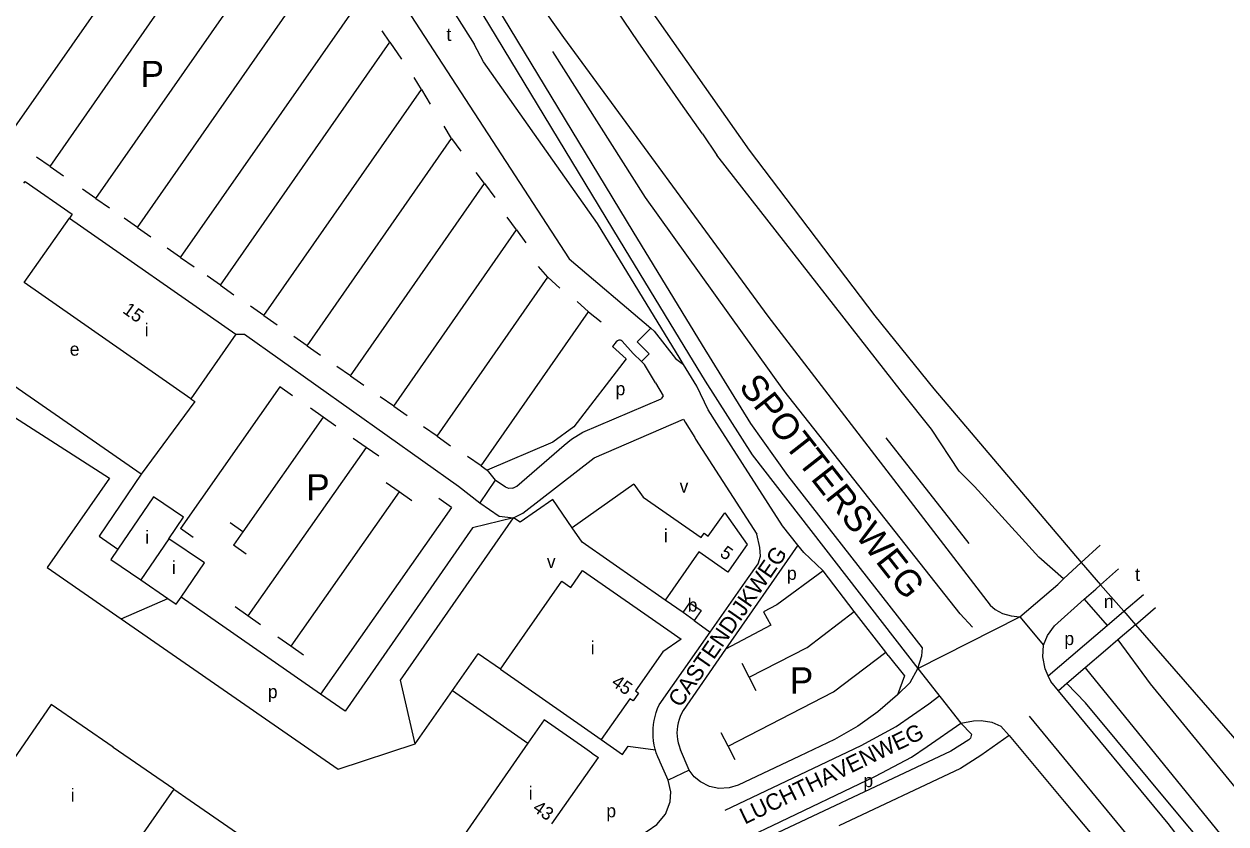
# Model space of a CAD drawing. Extents: x 154765 to 156627, y 383996 to 386132.
# Drawn here: x 155399 to 155766.1, y 385647.4 to 385891.7 of the extents above; entities that cross this region are included whole.
import ezdxf

# ---------------------------------------------------------------- set-up
doc = ezdxf.new("R2010")
doc.units = 0
for name, color, linetype in [('BLT_Basislijn', 7, 'Continuous'), ('BLT_Bebouwing', 7, 'Continuous'), ('BLT_Centroide', 7, 'Continuous'), ('BLT_Huisnummer', 7, 'Continuous'), ('BLT_Onderverdeling_panden', 7, 'Continuous'), ('BLT_Straatnaam', 7, 'Continuous'), ('BLT_Straatnaam_hoofdweg', 7, 'Continuous'), ('BLT_Tekst_parkeren', 7, 'Continuous'), ('BLT_Vlakafsluiter', 7, 'Continuous')]:
    doc.layers.add(name, color=color, linetype=linetype)

msp = doc.modelspace()

# ---------------------------------------------------------------- linework, layer by layer
at = {"layer": 'BLT_Basislijn'}
for p, q in [((155394.1, 385857.19), (155450.89, 385938.64)), ((155406.96, 385848.23), (155465.48, 385932.15)), ((155420.99, 385838.44), (155481.86, 385925.73)), ((155433.65, 385829.61), (155493.15, 385914.93)), ((155446.85, 385820.41), (155502.11, 385899.66)), ((155510.78, 385886.14), (155508.35, 385889.64)), ((155459.02, 385811.92), (155510.78, 385886.14)), ((155510.78, 385886.14), (155514.33, 385881.01)), ((155520.4, 385871.75), (155518.22, 385875.37)), ((155472.25, 385802.7), (155520.4, 385871.75)), ((155520.4, 385871.75), (155523.08, 385867.28)), ((155529.61, 385856.77), (155527.33, 385860.57)), ((155485.48, 385793.47), (155529.61, 385856.77)), ((155529.61, 385856.77), (155532.43, 385852.94)), ((155606.25, 385858.21), (155610.61, 385851.64)), ((155406.96, 385848.23), (155402.86, 385851.09)), ((155406.96, 385848.23), (155411.06, 385845.37)), ((155539.65, 385842.97), (155537.16, 385846.37)), ((155420.99, 385838.44), (155416.89, 385841.3)), ((155498.7, 385784.25), (155539.65, 385842.97)), ((155539.65, 385842.97), (155542.79, 385838.71)), ((155420.99, 385838.44), (155425.09, 385835.58)), ((155433.65, 385829.61), (155429.55, 385832.47)), ((155549.44, 385828.82), (155546.59, 385832.69)), ((155433.65, 385829.61), (155437.76, 385826.75)), ((155511.93, 385775.03), (155549.44, 385828.82)), ((155549.44, 385828.82), (155552.29, 385824.94)), ((155446.85, 385820.41), (155442.75, 385823.27)), ((155446.85, 385820.41), (155450.95, 385817.55)), ((155559.02, 385814.36), (155556.17, 385817.7)), ((155459.02, 385811.92), (155454.92, 385814.78)), ((155459.02, 385811.92), (155463.12, 385809.06)), ((155525.16, 385765.8), (155559.02, 385814.36)), ((155559.02, 385814.36), (155562.7, 385811.01)), ((155472.25, 385802.7), (155468.15, 385805.56)), ((155571.4, 385803.84), (155567.96, 385806.95)), ((155472.25, 385802.7), (155476.35, 385799.84)), ((155538.61, 385756.82), (155571.4, 385803.84)), ((155571.4, 385803.84), (155575.29, 385800.74)), ((155485.48, 385793.47), (155481.37, 385796.33)), ((155485.48, 385793.47), (155489.58, 385790.61)), ((155434.78, 385754.2), (155382.19, 385790.75)), ((155498.7, 385784.25), (155494.6, 385787.11)), ((155498.7, 385784.25), (155502.8, 385781.39)), ((155477.16, 385780.9), (155446.77, 385737.61)), ((155481.05, 385778.17), (155477.16, 385780.9)), ((155511.93, 385775.03), (155507.83, 385777.89)), ((155511.93, 385775.03), (155516.03, 385772.17)), ((155569.74, 385767.03), (155593.64, 385777.23)), ((155490.39, 385771.61), (155465.85, 385736.64)), ((155490.39, 385771.61), (155486.5, 385774.35)), ((155494.29, 385768.88), (155490.39, 385771.61)), ((155525.16, 385765.8), (155521.05, 385768.66)), ((155573.12, 385759.18), (155600.45, 385771.08)), ((155503.49, 385762.43), (155499.59, 385765.16)), ((155525.16, 385765.8), (155529.26, 385762.94)), ((155604.14, 385764.98), (155622.8, 385735.87)), ((155662.28, 385765.31), (155687.56, 385733.1)), ((155503.49, 385762.43), (155467.39, 385711)), ((155507.38, 385759.69), (155503.49, 385762.43)), ((155538.61, 385756.82), (155534.51, 385759.68)), ((155538.61, 385756.82), (155540.51, 385755.49)), ((155551.38, 385742.32), (155573.12, 385759.18)), ((155540.51, 385755.49), (155542.88, 385752.4)), ((155513.56, 385748.85), (155509.67, 385751.58)), ((155542.88, 385752.4), (155538.18, 385745.45)), ((155548.36, 385749.94), (155549.58, 385750.61)), ((155513.56, 385748.85), (155480.48, 385701.71)), ((155517.46, 385746.12), (155513.56, 385748.85)), ((155529.6, 385744.09), (155525.71, 385746.83)), ((155529.6, 385744.09), (155489.56, 385687.04)), ((155548.47, 385740.88), (155551.38, 385742.32)), ((155465.85, 385736.64), (155461.95, 385739.38)), ((155450.67, 385734.88), (155446.77, 385737.61)), ((155465.85, 385736.64), (155462.95, 385732.52)), ((155466.85, 385729.79), (155462.95, 385732.52)), ((155635.4, 385732.55), (155613.31, 385700.75)), ((155721.95, 385727.25), (155727.72, 385732.59)), ((155716.54, 385722.25), (155721.95, 385727.25)), ((155406.09, 385725.78), (155428.73, 385710.08)), ((155652.6, 385712.32), (155643.08, 385724.72)), ((155727.84, 385720.48), (155733.32, 385725.31)), ((155608.62, 385706.02), (155620, 385722.24)), ((155703.21, 385710.66), (155714.74, 385720.58)), ((155714.74, 385720.58), (155716.54, 385722.25)), ((155726.35, 385719.17), (155727.84, 385720.48)), ((155727.84, 385720.48), (155734.89, 385712.38)), ((155428.73, 385710.08), (155442.95, 385716.28)), ((155489.56, 385687.04), (155446.96, 385716.65)), ((155722.81, 385716.02), (155726.35, 385719.17)), ((155734.89, 385712.38), (155740.98, 385717.5)), ((155467.39, 385711), (155463.5, 385713.73)), ((155600.3, 385711.96), (155594.87, 385715.74)), ((155722.81, 385716.02), (155729.8, 385708.02)), ((155738.49, 385708.23), (155744.6, 385713.56)), ((155471.28, 385708.27), (155467.39, 385711)), ((155603.7, 385709.59), (155608.62, 385706.02)), ((155638.17, 385701.31), (155652.6, 385712.32)), ((155662.19, 385699.84), (155652.6, 385712.32)), ((155729.8, 385708.02), (155734.89, 385712.38)), ((155711.87, 385692.63), (155729.8, 385708.02)), ((155738.49, 385708.23), (155733.11, 385703.62)), ((155738.49, 385708.23), (155841.63, 385589.61)), ((155480.48, 385701.71), (155476.58, 385704.44)), ((155484.37, 385698.98), (155480.48, 385701.71)), ((155733.11, 385703.62), (155729.31, 385700.36)), ((155529.88, 385688.16), (155537.72, 385699.39)), ((155544.51, 385694.65), (155537.72, 385699.39)), ((155613.31, 385700.75), (155600.34, 385682.06)), ((155646.3, 385687.72), (155662.19, 385699.84)), ((155662.91, 385698.9), (155662.19, 385699.84)), ((155729.31, 385700.36), (155723.16, 385695.09)), ((155620.54, 385692.23), (155618.4, 385696.38)), ((155723.16, 385695.09), (155717.53, 385690.26)), ((155723.16, 385695.09), (155782.92, 385621.52)), ((155622.68, 385688.08), (155620.54, 385692.23)), ((155518.47, 385671.84), (155529.88, 385688.16)), ((155529.88, 385688.16), (155552.89, 385672.11)), ((155717.53, 385690.26), (155714.99, 385688.08)), ((155723.18, 385684.36), (155717.53, 385690.26)), ((155751.97, 385649.86), (155723.18, 385684.36)), ((155614.08, 385671.13), (155611.94, 385675.28)), ((155602.17, 385663.86), (155599.53, 385670.08)), ((155616.22, 385666.98), (155614.08, 385671.13)), ((155777.49, 385619.55), (155751.97, 385649.86))]:
    msp.add_line(p, q, dxfattribs=at)
for points in [[(155436.46, 386122.26), (155447.02, 386098.46), (155464.73, 386060.92), (155502.12, 385988.55), (155522.93, 385949.4), (155547.79, 385910.16), (155563.82, 385887.59), (155626.16, 385802.48), (155694.08, 385714.21), (155695.64, 385712.93), (155697.9, 385711.66), (155700.48, 385711), (155703.21, 385710.66)], [(155673.43, 385701.24), (155632.28, 385753.88), (155620.97, 385769.74), (155606.23, 385793.62), (155585.03, 385828.39), (155543.47, 385897.08), (155528.33, 385922.4), (155507.19, 385957.56), (155492.82, 385984.34), (155458.25, 386051.13), (155428.82, 386114.16), (155427.04, 386118.17)], [(155422.92, 386115.12), (155424.27, 386112.09), (155453.76, 386048.92), (155488.4, 385982), (155502.84, 385955.08), (155524.05, 385919.83), (155539.19, 385894.5), (155580.76, 385825.8), (155596.28, 385800.34)], [(155606.25, 385858.21), (155599.63, 385867.52), (155593.07, 385876.88), (155586.57, 385886.29), (155580.15, 385895.75), (155573.79, 385905.25), (155567.49, 385914.79), (155561.26, 385924.38), (155555.1, 385934.01), (155549.01, 385943.68), (155542.98, 385953.4), (155537.02, 385963.16), (155531.14, 385972.96), (155525.32, 385982.8), (155519.57, 385992.68), (155513.88, 386002.6), (155510.64, 386008.34)], [(155443.24, 385953.72), (155447.55, 385963.96), (155495.21, 385946.79), (155498.36, 385944.72), (155505.15, 385934.83), (155511.09, 385925.92), (155536.49, 385885.57)], [(155492.35, 385932.56), (155565.52, 385819.97), (155590.44, 385798.8)], [(155587.72, 385899.93), (155620.49, 385853.18), (155658.88, 385802.59)], [(155574.19, 385830.82), (155539.31, 385880.22), (155536.49, 385885.57)], [(155688.7, 385707.54), (155684.91, 385711.58), (155631.13, 385779.81), (155588.83, 385838.73), (155560.52, 385883.37)], [(155716.54, 385722.25), (155709, 385728.92), (155694.62, 385744.67), (155689.33, 385750.48), (155684.62, 385755.19), (155676.22, 385767.96), (155667.32, 385779.09), (155610.61, 385851.64)], [(155398.93, 385843.08), (155399.32, 385843.64), (155413.7, 385833.64), (155412.85, 385832.42)], [(155600.45, 385787.76), (155599.41, 385789.44), (155574.19, 385830.82)], [(155658.88, 385802.59), (155676.87, 385780.3), (155721.95, 385727.25)], [(155463.68, 385797.03), (155466.36, 385797.04), (155531.71, 385750.56), (155538.18, 385745.45)], [(155587.62, 385788.62), (155589.99, 385791.01), (155586.32, 385794.65), (155590.44, 385798.8)], [(155590.44, 385798.8), (155591.43, 385797.96), (155598.04, 385789.59), (155600.45, 385787.76)], [(155596.28, 385800.34), (155601.96, 385791.01), (155607.1, 385782.68)], [(155587.62, 385788.62), (155585.08, 385791.12), (155581.67, 385794.87), (155581.39, 385795.03), (155581.18, 385795.14), (155580.92, 385795.18), (155580.68, 385795.15), (155580.31, 385794.97), (155579.87, 385794.67), (155578.72, 385793.25), (155582.93, 385789.44), (155566.99, 385768.74)], [(155326.29, 385719.84), (155372.64, 385786.64), (155425.08, 385753.07), (155406.09, 385725.78)], [(155591.89, 385782.14), (155588.55, 385787.7), (155587.62, 385788.62)], [(155635.4, 385732.55), (155630.65, 385738.44), (155610.62, 385769.68), (155607.95, 385773.94), (155604.55, 385781.11), (155600.45, 385787.76)], [(155607.1, 385782.68), (155621.45, 385760.13), (155672.06, 385694.92)], [(155591.89, 385782.14), (155594.23, 385778.21), (155593.64, 385777.23)], [(155449.93, 385777.26), (155451.15, 385776.41), (155434.78, 385754.2)], [(155566.99, 385768.74), (155560.51, 385764), (155540.51, 385755.49)], [(155600.45, 385771.08), (155600.93, 385770.08), (155603.87, 385765.39), (155604.14, 385764.98)], [(155549.58, 385750.61), (155563.98, 385763.14), (155566.22, 385764.91), (155569.74, 385767.03)], [(155434.78, 385754.2), (155421.91, 385735.26), (155427.71, 385731.32)], [(155548.36, 385749.94), (155547.11, 385749.9), (155546.05, 385750.25), (155542.88, 385752.4)], [(155566.39, 385737.9), (155560.51, 385746.46), (155550.55, 385739.62), (155548.47, 385740.88)], [(155538.18, 385745.45), (155544.09, 385741.45), (155548.47, 385740.88)], [(155548.47, 385740.88), (155536, 385737.81), (155497.07, 385681.81), (155489.56, 385687.04)], [(155518.47, 385671.84), (155513.99, 385691.36), (155548.47, 385740.88)], [(155620, 385722.24), (155623.27, 385726.89), (155623.98, 385729.15), (155623.77, 385731.86), (155622.8, 385735.87)], [(155643.08, 385724.72), (155643, 385724.82), (155637.21, 385730.31), (155635.4, 385732.55)], [(155643.08, 385724.72), (155628.98, 385714.37), (155624.89, 385712.18), (155627.07, 385708.09), (155613.31, 385700.75)], [(155710.42, 385702), (155711.62, 385705.01), (155713.74, 385707.95), (155722.81, 385716.02)], [(155428.73, 385710.08), (155494.99, 385664.13), (155518.47, 385671.84)], [(155591.84, 385670.1), (155591.78, 385670.29), (155591.5, 385671.52), (155591.3, 385672.76), (155591.17, 385674.02), (155591.13, 385675.28), (155591.16, 385676.54), (155591.28, 385677.79), (155591.47, 385679.04), (155591.74, 385680.26), (155592.1, 385681.48), (155592.52, 385682.66), (155593.02, 385683.82), (155608.62, 385706.02)], [(155711.87, 385692.63), (155710.86, 385694.81), (155710.16, 385698.48), (155710.42, 385702)], [(155733.11, 385703.62), (155742.99, 385690.24), (155782.23, 385642.23), (156011.28, 385380.1), (156036.1, 385355.51)], [(155620.54, 385692.23), (155638.17, 385701.31)], [(155662.91, 385698.9), (155667.98, 385692.65), (155665.85, 385686.82)], [(155672.06, 385694.92), (155673.19, 385698.79), (155673.43, 385701.24)], [(155665.85, 385686.82), (155669.66, 385690.65), (155672.06, 385694.92)], [(155714.99, 385688.08), (155712.68, 385690.88), (155711.87, 385692.63)], [(155665.85, 385686.82), (155659.82, 385681.66), (155653.67, 385677.31), (155646.54, 385673.23), (155635.86, 385668.12), (155617.12, 385659.23), (155614.42, 385658.4), (155611.24, 385658.25), (155608.37, 385658.86), (155605.61, 385660.24), (155603.7, 385661.84), (155602.17, 385663.86)], [(155614.08, 385671.13), (155646.3, 385687.72)], [(156007.6, 385344.92), (155996.28, 385354.88), (155980.49, 385371.12), (155972.14, 385379.04), (155965.68, 385384.27), (155957.28, 385390.42), (155944.89, 385398.75), (155936.89, 385404.83), (155929.87, 385410.58), (155925.23, 385414.81), (155918.35, 385421.09), (155902.63, 385438.73), (155854.03, 385494.81), (155800.47, 385556.64), (155793.89, 385564.54), (155785.69, 385576.1), (155777.93, 385590.57), (155771.46, 385606.33), (155765, 385622.09), (155759.19, 385632.12), (155752.51, 385642.23), (155748.51, 385647.55), (155714.99, 385688.08)], [(155613.17, 385651.67), (155654.74, 385671.33), (155665.37, 385677.19), (155675.36, 385684.07), (155678.4, 385686.49)], [(155600.34, 385682.06), (155599.84, 385681.17), (155599.42, 385680.24), (155599.07, 385679.28), (155598.79, 385678.3), (155598.6, 385677.3), (155598.48, 385676.28), (155598.44, 385675.26), (155598.49, 385674.24), (155598.61, 385673.23), (155598.81, 385672.23), (155599.09, 385671.25), (155599.45, 385670.29), (155599.53, 385670.08)], [(155705.97, 385680.31), (155735.54, 385644.51), (155745.02, 385632.44), (155750.86, 385623.61), (155756.86, 385613.62), (155765.1, 385597.81)], [(155616.86, 385638.87), (155618.82, 385641.82), (155621.63, 385644.09), (155627.62, 385646.96), (155659.11, 385662), (155670.08, 385667.83), (155674.86, 385671.1), (155685.15, 385678.21)], [(155685.15, 385678.21), (155688.97, 385678.86), (155691.38, 385678.96), (155694.59, 385678.46), (155697.36, 385677.28), (155699.96, 385674.45)], [(155685.15, 385678.21), (155688.42, 385674.79), (155688.15, 385673.62)], [(155575.32, 385673.17), (155581.82, 385668.65), (155583.58, 385671.2), (155591.84, 385670.1)], [(155688.15, 385673.62), (155687.58, 385673.11), (155682.11, 385669.63), (155616.86, 385638.87)], [(155699.96, 385674.45), (155691.21, 385668.31), (155685.01, 385664.36), (155647.86, 385646.85)], [(155699.96, 385674.45), (155716.73, 385654.28), (155725.17, 385644.24), (155735.98, 385631.29), (155744.84, 385618.79), (155753.89, 385602.72), (155760.37, 385591.15), (155767.75, 385580.16), (155776.01, 385569.79), (155821.88, 385516.23)], [(155595.72, 385660.82), (155593.31, 385666.3), (155593.09, 385666.75), (155592.58, 385667.9), (155592.14, 385669.09), (155591.84, 385670.1)], [(155575.39, 385636.61), (155589.29, 385645.25), (155592.25, 385647.23), (155594.99, 385650.37), (155596.39, 385654.14), (155596.54, 385657.23), (155595.72, 385660.82)]]:
    msp.add_lwpolyline(points, dxfattribs=at)
at = {"layer": 'BLT_Bebouwing'}
for p, q in [((155412.85, 385832.42), (155463.68, 385797.03)), ((155463.68, 385797.03), (155449.93, 385777.26)), ((155434.66, 385721.93), (155442.95, 385716.28)), ((155444.78, 385658.01), (155449.72, 385654.59))]:
    msp.add_line(p, q, dxfattribs=at)
for points in [[(155449.93, 385777.26), (155399.09, 385812.73), (155412.85, 385832.42)], [(155585.3, 385751.21), (155566.39, 385737.9)], [(155585.3, 385751.21), (155588.12, 385747.25), (155605.81, 385734.94), (155606.73, 385736.24), (155608.02, 385735.32)], [(155443.26, 385734.53), (155447.71, 385741.06), (155438.59, 385747.28), (155427.71, 385731.32)], [(155608.02, 385735.32), (155613.02, 385742.46)], [(155613.02, 385742.46), (155619.88, 385732.75), (155615.09, 385725.9)], [(155446.96, 385716.65), (155454.13, 385727.13), (155443.26, 385734.53)], [(155594.87, 385715.74), (155569.48, 385733.49), (155566.39, 385737.9)], [(155427.71, 385731.32), (155425.55, 385728.14), (155434.66, 385721.93)], [(155605.16, 385730.49), (155594.87, 385715.74)], [(155615.09, 385725.9), (155614, 385724.34), (155605.16, 385730.49)], [(155544.51, 385694.65), (155548.23, 385700), (155563.25, 385721.56), (155566, 385719.65), (155569.6, 385724.81)], [(155569.6, 385724.81), (155595.61, 385706.68), (155599.71, 385703.82), (155594.14, 385700), (155585.76, 385688.02), (155586.66, 385687.38), (155585.02, 385685.01), (155584.09, 385685.64), (155575.32, 385673.17)], [(155442.95, 385716.28), (155445.51, 385714.53), (155446.96, 385716.65)], [(155600.3, 385711.96), (155602.42, 385714.98)], [(155602.42, 385714.98), (155605.81, 385712.61), (155603.7, 385709.59)], [(155603.7, 385709.59), (155600.3, 385711.96)], [(155544.51, 385694.65), (155571.22, 385676.03), (155575.32, 385673.17)], [(155426.25, 385670.81), (155426.2, 385670.85), (155407.34, 385683.88), (155381.71, 385646.8)], [(155572.45, 385669.06), (155570.35, 385670.53), (155557.84, 385679.22), (155552.89, 385672.11)], [(155552.89, 385672.11), (155531.87, 385641.88)], [(155444.78, 385658.01), (155426.25, 385670.81)], [(155572.45, 385669.06), (155574.45, 385667.67)], [(155560.27, 385647.4), (155574.45, 385667.67)], [(155449.72, 385654.59), (155491.46, 385625.74), (155495.57, 385622.9)]]:
    msp.add_lwpolyline(points, dxfattribs=at)
at = {"layer": 'BLT_Onderverdeling_panden'}
for p, q in [((155443.26, 385734.53), (155434.66, 385721.93)), ((155444.78, 385658.01), (155426.64, 385632.06))]:
    msp.add_line(p, q, dxfattribs=at)
at = {"layer": 'BLT_Vlakafsluiter'}
for p, q in [((155721.95, 385727.25), (155727.84, 385720.48)), ((155672.06, 385694.92), (155703.21, 385710.66)), ((155703.21, 385710.66), (155710.42, 385702)), ((155734.89, 385712.38), (155738.49, 385708.23)), ((155672.06, 385694.92), (155685.15, 385678.21)), ((155602.17, 385663.86), (155595.72, 385660.82))]:
    msp.add_line(p, q, dxfattribs=at)

# ---------------------------------------------------------------- texts
at = {"layer": 'BLT_Centroide'}
for s, p in [('t', (155528.03, 385886.56)), ('i', (155435.87, 385796.31)), ('e', (155412.97, 385790.43)), ('p', (155579.69, 385778.34)), ('v', (155599.25, 385748.61)), ('i', (155436.01, 385733.01)), ('i', (155594.44, 385733.47)), ('i', (155444.17, 385723.75)), ('v', (155558.7, 385725.57)), ('p', (155632.04, 385721.96)), ('t', (155738.39, 385721.65)), ('b', (155601.72, 385712.28)), ('n', (155728.82, 385713.38)), ('p', (155716.78, 385702.05)), ('i', (155572.11, 385699.23)), ('p', (155473.48, 385685.82)), ('p', (155655.39, 385658.66)), ('i', (155413.27, 385654.22)), ('i', (155553.16, 385654.86)), ('p', (155576.87, 385649.43))]:
    msp.add_text(s, height=4, dxfattribs=at).set_placement(p)
at = {"layer": 'BLT_Huisnummer'}
for s, rotation, p in [('15', 324.6661, (155428.86, 385803.72)), ('5', 324.6661, (155611.27, 385729.43)), ('45', 325.116, (155578.13, 385689.95)), ('43', 325.1897, (155554.09, 385651.6))]:
    msp.add_text(s, height=4, rotation=rotation, dxfattribs=at).set_placement(p)
at = {"layer": 'BLT_Straatnaam'}
for s, rotation, p in [('CASTENDIJKWEG', 55.2224, (155599.49, 385682.71)), ('LUCHTHAVENWEG', 25.7889, (155619.16, 385647.18))]:
    msp.add_text(s, height=5, rotation=rotation, dxfattribs=at).set_placement(p)
at = {"layer": 'BLT_Straatnaam_hoofdweg'}
msp.add_text('SPOTTERSWEG', height=8, rotation=308.1, dxfattribs=at).set_placement((155617.08, 385780.87))
at = {"layer": 'BLT_Tekst_parkeren'}
for p in [(155434.62, 385872.47), (155485.22, 385746.22), (155632.93, 385687.24)]:
    msp.add_text('P', height=8, rotation=359.9654, dxfattribs=at).set_placement(p)

doc.saveas('drawing.dxf')
